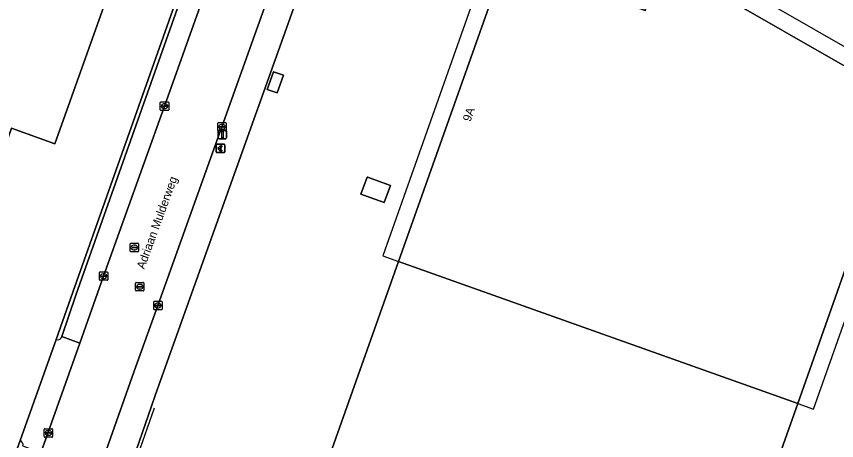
# Model space of a CAD drawing. Extents: x 155018 to 156648, y 383979 to 385733.
# Drawn here: x 155717.1 to 155814.3, y 385021.6 to 385071.8 of the extents above; entities that cross this region are included whole.
import ezdxf

# ---------------------------------------------------------------- set-up
doc = ezdxf.new("R2010")
doc.units = 0
for name, color, linetype in [('IMGEO_Betaalautomaat', 7, 'Continuous'), ('IMGEO_Erf', 7, 'Continuous'), ('IMGEO_Hek', 7, 'Continuous'), ('IMGEO_Kolk', 7, 'Continuous'), ('IMGEO_Lage_trafo', 7, 'Continuous'), ('IMGEO_Lichtmast', 7, 'Continuous'), ('IMGEO_Openbare_ruimte_label', 7, 'Continuous'), ('IMGEO_Pand', 7, 'Continuous'), ('IMGEO_Pand_nummerreeks', 7, 'Continuous'), ('IMGEO_Pand_overbouw', 7, 'Continuous'), ('IMGEO_Parkeervlak_open', 7, 'Continuous'), ('IMGEO_Rijbaan_lokaal_gesloten', 7, 'Continuous'), ('IMGEO_Rioolput', 7, 'Continuous'), ('IMGEO_Voetpad_open', 7, 'Continuous')]:
    doc.layers.add(name, color=color, linetype=linetype)

msp = doc.modelspace()

# ---------------------------------------------------------------- linework, layer by layer
at = {"layer": 'IMGEO_Betaalautomaat'}
for p, q in [((155740.767, 385055.78), (155740.767, 385056.621)), ((155740.767, 385056.621), (155740.767, 385055.78)), ((155740.842, 385056.704), (155741.683, 385056.704)), ((155741.683, 385056.704), (155740.842, 385056.704)), ((155741.05, 385056.168), (155741.05, 385056.236)), ((155741.171, 385056.236), (155741.171, 385056.168)), ((155741.429, 385056.509), (155741.412, 385056.409)), ((155741.416, 385056.003), (155741.438, 385055.916)), ((155741.766, 385056.63), (155741.766, 385055.789)), ((155741.766, 385055.789), (155741.766, 385056.63)), ((155741.692, 385055.705), (155740.851, 385055.705)), ((155740.851, 385055.705), (155741.692, 385055.705))]:
    msp.add_line(p, q, dxfattribs=at)
for points in [[(155741.05, 385056.236), (155740.981, 385056.236), (155740.981, 385056.305), (155741.06, 385056.305)], [(155741.055, 385056.099), (155740.981, 385056.099), (155740.981, 385056.168), (155741.05, 385056.168)], [(155741.182, 385056.305), (155741.329, 385056.305), (155741.329, 385056.236), (155741.171, 385056.236)], [(155741.171, 385056.168), (155741.329, 385056.168), (155741.329, 385056.099), (155741.185, 385056.099)]]:
    msp.add_lwpolyline(points, dxfattribs=at)
for centre, radius, start, end in [((155740.845, 385056.627), 0.0779, 92.4484, 184.28452), ((155740.845, 385056.627), 0.0779, 92.4484, 184.28452), ((155741.316, 385056.154), 0.267, 191.80956, 297.03891), ((155741.343, 385056.229), 0.293, 73.01398, 165.01395), ((155741.349, 385056.242), 0.179, 69.32359, 159.56827), ((155741.349, 385056.169), 0.179, 202.76249, 291.86925), ((155741.689, 385056.627), 0.0779, 2.4484, 94.28452), ((155741.689, 385056.627), 0.0779, 2.4484, 94.28452), ((155740.845, 385055.783), 0.0779, 182.4484, 274.28452), ((155740.845, 385055.783), 0.0779, 182.4484, 274.28452), ((155741.689, 385055.783), 0.0779, 272.4484, 4.28452), ((155741.689, 385055.783), 0.0779, 272.4484, 4.28452)]:
    msp.add_arc(centre, radius, start, end, dxfattribs=at)
at = {"layer": 'IMGEO_Erf'}
for points in [[(155694.342, 384956.978), (155694.915, 384958.585), (155709.077, 384998.076), (155709.767, 385000), (155717.522, 385021.627), (155721.797, 385033.581), (155723.78, 385039.191), (155749.439, 385111.623), (155754.279, 385125.284), (155751.396, 385130.416), (155717.596, 385142.395), (155670.014, 385159.249), (155661.245, 385162.355), (155620.236, 385176.93), (155602.298, 385183.305), (155601.269, 385183.671), (155551.448, 385201.401), (155546.604, 385198.733), (155542.42, 385187.249), (155529.708, 385151.464), (155526.702, 385143.011), (155526.061, 385141.208), (155524.297, 385136.458), (155523.434, 385136.779)], [(155841.725, 385076.189), (155812.458, 385090.276), (155811.925, 385090.532), (155810.841, 385091.052), (155764.43, 385113.324), (155764.255, 385112.835), (155733.568, 385027.069), (155733.054, 385025.589), (155730.642, 385018.653)], [(155753.183, 385017.001), (155762.359, 385042.817), (155775.007, 385078.407), (155791.593, 385072.523), (155793.619, 385078.32), (155822.361, 385061.864), (155809.649, 385026.028), (155797.027, 384990.446)]]:
    msp.add_lwpolyline(points, dxfattribs=at)
for points in [[(155670.263, 385124.691), (155674.13, 385128.38), (155672.13, 385129.15), (155674.66, 385131.64), (155676.67, 385130.92), (155681.04, 385135.1), (155695.29, 385130.022), (155721.45, 385120.7), (155719.12, 385114.03), (155729.74, 385110.24), (155731.69, 385106.03), (155727.91, 385095.51), (155734.56, 385093.08), (155727.662, 385073.693), (155721.63, 385056.74), (155716.5, 385058.59), (155715.32, 385055.2), (155712.89, 385057.75), (155713.52, 385059.62), (155709.03, 385061.25), (155718.594, 385088.148), (155701.503, 385094.257), (155707.612, 385111.348)], [(155747.968, 385062.78), (155746.814, 385063.191), (155747.549, 385065.252), (155748.711, 385064.866)], [(155757.908, 385050.806), (155758.646, 385052.82), (155758.671, 385052.811), (155761.411, 385051.807), (155760.673, 385049.793)]]:
    msp.add_lwpolyline(points, close=True, dxfattribs=at)
at = {"layer": 'IMGEO_Hek'}
msp.add_lwpolyline([(155733.417, 385025.46), (155730.074, 385015.981), (155724.402, 385000)], dxfattribs=at)
at = {"layer": 'IMGEO_Kolk'}
for p, q in [((155734.132, 385060.779), (155734.132, 385061.631)), ((155734.207, 385061.705), (155735.059, 385061.705)), ((155734.391, 385061.199), (155734.391, 385061.211)), ((155734.829, 385061.162), (155734.431, 385061.162)), ((155734.434, 385061.248), (155734.832, 385061.248)), ((155734.643, 385060.925), (155734.618, 385060.925)), ((155734.62, 385061.485), (155734.645, 385061.485)), ((155734.875, 385061.211), (155734.875, 385061.199)), ((155735.133, 385061.631), (155735.133, 385060.779)), ((155735.059, 385060.705), (155734.207, 385060.705)), ((155740.94, 385058.342), (155740.94, 385059.194)), ((155741.015, 385059.268), (155741.867, 385059.268)), ((155741.428, 385059.048), (155741.453, 385059.048)), ((155741.941, 385059.194), (155741.941, 385058.342)), ((155741.867, 385058.268), (155741.015, 385058.268)), ((155741.199, 385058.762), (155741.199, 385058.774)), ((155741.637, 385058.725), (155741.239, 385058.725)), ((155741.242, 385058.811), (155741.64, 385058.811)), ((155741.451, 385058.488), (155741.426, 385058.488)), ((155741.683, 385058.774), (155741.683, 385058.762)), ((155726.918, 385040.669), (155726.918, 385041.521)), ((155726.993, 385041.595), (155727.845, 385041.595)), ((155727.406, 385041.375), (155727.431, 385041.375)), ((155727.919, 385041.521), (155727.919, 385040.669)), ((155727.845, 385040.595), (155726.993, 385040.595)), ((155727.177, 385041.089), (155727.177, 385041.101)), ((155727.615, 385041.052), (155727.217, 385041.052)), ((155727.22, 385041.138), (155727.618, 385041.138)), ((155727.429, 385040.815), (155727.404, 385040.815)), ((155727.661, 385041.101), (155727.661, 385041.089)), ((155733.348, 385037.188), (155733.348, 385038.04)), ((155733.423, 385038.114), (155734.275, 385038.114)), ((155733.607, 385037.608), (155733.607, 385037.62)), ((155734.045, 385037.571), (155733.647, 385037.571)), ((155733.65, 385037.657), (155734.048, 385037.657)), ((155733.836, 385037.894), (155733.861, 385037.894)), ((155734.091, 385037.62), (155734.091, 385037.608)), ((155734.349, 385038.04), (155734.349, 385037.188)), ((155734.275, 385037.114), (155733.423, 385037.114)), ((155733.859, 385037.334), (155733.834, 385037.334)), ((155720.374, 385022.102), (155720.374, 385022.954)), ((155720.449, 385023.028), (155721.301, 385023.028)), ((155721.375, 385022.954), (155721.375, 385022.102)), ((155721.301, 385022.028), (155720.449, 385022.028)), ((155720.633, 385022.522), (155720.633, 385022.534)), ((155721.071, 385022.485), (155720.673, 385022.485)), ((155720.676, 385022.571), (155721.074, 385022.571)), ((155720.885, 385022.248), (155720.86, 385022.248)), ((155720.862, 385022.808), (155720.887, 385022.808)), ((155721.117, 385022.534), (155721.117, 385022.522))]:
    msp.add_line(p, q, dxfattribs=at)
for points in [[(155734.132, 385060.779), (155734.132, 385061.631)], [(155734.207, 385061.705), (155735.059, 385061.705)], [(155735.133, 385061.631), (155735.133, 385060.779)], [(155735.059, 385060.705), (155734.207, 385060.705)], [(155740.94, 385058.342), (155740.94, 385059.194)], [(155741.015, 385059.268), (155741.867, 385059.268)], [(155741.941, 385059.194), (155741.941, 385058.342)], [(155741.867, 385058.268), (155741.015, 385058.268)], [(155726.918, 385040.669), (155726.918, 385041.521)], [(155726.993, 385041.595), (155727.845, 385041.595)], [(155727.919, 385041.521), (155727.919, 385040.669)], [(155727.845, 385040.595), (155726.993, 385040.595)], [(155733.348, 385037.188), (155733.348, 385038.04)], [(155733.423, 385038.114), (155734.275, 385038.114)], [(155734.349, 385038.04), (155734.349, 385037.188)], [(155734.275, 385037.114), (155733.423, 385037.114)], [(155720.374, 385022.102), (155720.374, 385022.954)], [(155720.449, 385023.028), (155721.301, 385023.028)], [(155721.375, 385022.954), (155721.375, 385022.102)], [(155721.301, 385022.028), (155720.449, 385022.028)]]:
    msp.add_lwpolyline(points, dxfattribs=at)
for centre, radius, start, end in [((155734.209, 385061.629), 0.0765, 91.55205, 178.44795), ((155734.209, 385061.629), 0.0765, 91.55205, 178.44795), ((155734.431, 385061.208), 0.0403, 85.87752, 175.75265), ((155734.428, 385061.198), 0.0366, 178.93798, 274.71019), ((155734.832, 385061.205), 0.043, 264.86636, 352.45326), ((155734.836, 385061.21), 0.0386, 1.73085, 96.63898), ((155735.057, 385061.629), 0.0765, 1.55205, 88.44795), ((155735.057, 385061.629), 0.0765, 1.55205, 88.44795), ((155734.209, 385060.781), 0.0765, 181.55205, 268.44795), ((155734.209, 385060.781), 0.0765, 181.55205, 268.44795), ((155735.057, 385060.781), 0.0765, 271.55205, 358.44795), ((155735.057, 385060.781), 0.0765, 271.55205, 358.44795), ((155741.017, 385059.192), 0.0765, 91.55205, 178.44795), ((155741.017, 385059.192), 0.0765, 91.55205, 178.44795), ((155741.865, 385059.192), 0.0765, 1.55205, 88.44795), ((155741.865, 385059.192), 0.0765, 1.55205, 88.44795), ((155741.017, 385058.344), 0.0765, 181.55205, 268.44795), ((155741.017, 385058.344), 0.0765, 181.55205, 268.44795), ((155741.239, 385058.771), 0.0403, 85.87752, 175.75265), ((155741.236, 385058.761), 0.0366, 178.93798, 274.71019), ((155741.64, 385058.768), 0.043, 264.86636, 352.45326), ((155741.644, 385058.773), 0.0386, 1.73085, 96.63898), ((155741.865, 385058.344), 0.0765, 271.55205, 358.44795), ((155741.865, 385058.344), 0.0765, 271.55205, 358.44795), ((155726.995, 385041.519), 0.0765, 91.55205, 178.44795), ((155726.995, 385041.519), 0.0765, 91.55205, 178.44795), ((155727.843, 385041.519), 0.0765, 1.55205, 88.44795), ((155727.843, 385041.519), 0.0765, 1.55205, 88.44795), ((155726.995, 385040.671), 0.0765, 181.55205, 268.44795), ((155726.995, 385040.671), 0.0765, 181.55205, 268.44795), ((155727.217, 385041.098), 0.0403, 85.87752, 175.75265), ((155727.214, 385041.088), 0.0366, 178.93798, 274.71019), ((155727.618, 385041.095), 0.043, 264.86636, 352.45326), ((155727.622, 385041.1), 0.0386, 1.73085, 96.63898), ((155727.843, 385040.671), 0.0765, 271.55205, 358.44795), ((155727.843, 385040.671), 0.0765, 271.55205, 358.44795), ((155733.425, 385038.038), 0.0765, 91.55205, 178.44795), ((155733.425, 385038.038), 0.0765, 91.55205, 178.44795), ((155733.647, 385037.617), 0.0403, 85.87752, 175.75265), ((155733.644, 385037.607), 0.0366, 178.93798, 274.71019), ((155734.048, 385037.614), 0.043, 264.86636, 352.45326), ((155734.052, 385037.619), 0.0386, 1.73085, 96.63898), ((155734.273, 385038.038), 0.0765, 1.55205, 88.44795), ((155734.273, 385038.038), 0.0765, 1.55205, 88.44795), ((155733.425, 385037.19), 0.0765, 181.55205, 268.44795), ((155733.425, 385037.19), 0.0765, 181.55205, 268.44795), ((155734.273, 385037.19), 0.0765, 271.55205, 358.44795), ((155734.273, 385037.19), 0.0765, 271.55205, 358.44795), ((155720.451, 385022.952), 0.0765, 91.55205, 178.44795), ((155720.451, 385022.952), 0.0765, 91.55205, 178.44795), ((155721.299, 385022.952), 0.0765, 1.55205, 88.44795), ((155721.299, 385022.952), 0.0765, 1.55205, 88.44795), ((155720.451, 385022.104), 0.0765, 181.55205, 268.44795), ((155720.451, 385022.104), 0.0765, 181.55205, 268.44795), ((155720.673, 385022.531), 0.0403, 85.87752, 175.75265), ((155720.67, 385022.521), 0.0366, 178.93798, 274.71019), ((155721.074, 385022.528), 0.043, 264.86636, 352.45326), ((155721.078, 385022.533), 0.0386, 1.73085, 96.63898), ((155721.299, 385022.104), 0.0765, 271.55205, 358.44795), ((155721.299, 385022.104), 0.0765, 271.55205, 358.44795)]:
    msp.add_arc(centre, radius, start, end, dxfattribs=at)
for centre, major_axis, ratio, start_param, end_param in [((155734.619, 385061.205), (-0.387, 0.002), 0.722429, 4.712389, 7.853982), ((155734.644, 385061.205), (-0.39, 0.002), 0.717154, 1.570796, 4.712389), ((155741.427, 385058.768), (-0.387, 0.002), 0.722429, 4.712389, 7.853982), ((155741.452, 385058.768), (-0.39, 0.002), 0.717154, 1.570796, 4.712389), ((155727.405, 385041.095), (-0.387, 0.002), 0.722429, 4.712389, 7.853982), ((155727.43, 385041.095), (-0.39, 0.002), 0.717154, 1.570796, 4.712389), ((155733.835, 385037.614), (-0.387, 0.002), 0.722429, 4.712389, 7.853982), ((155733.86, 385037.614), (-0.39, 0.002), 0.717154, 1.570796, 4.712389), ((155720.861, 385022.528), (-0.387, 0.002), 0.722429, 4.712389, 7.853982), ((155720.886, 385022.528), (-0.39, 0.002), 0.717154, 1.570796, 4.712389)]:
    msp.add_ellipse(centre, major_axis=major_axis, ratio=ratio, start_param=start_param, end_param=end_param, dxfattribs=at)
at = {"layer": 'IMGEO_Lage_trafo'}
for points in [[(155747.549, 385065.252), (155746.814, 385063.191), (155747.968, 385062.78), (155748.711, 385064.866)], [(155758.646, 385052.82), (155757.908, 385050.806), (155760.673, 385049.793), (155761.411, 385051.807), (155758.671, 385052.811)]]:
    msp.add_lwpolyline(points, close=True, dxfattribs=at)
at = {"layer": 'IMGEO_Lichtmast'}
for p, q in [((155740.995, 385057.449), (155740.995, 385058.249)), ((155740.995, 385058.249), (155740.995, 385057.449)), ((155741.095, 385058.349), (155741.885, 385058.349)), ((155741.885, 385058.349), (155741.095, 385058.349)), ((155741.985, 385058.249), (155741.985, 385057.449)), ((155741.985, 385057.449), (155741.985, 385058.249)), ((155741.885, 385057.349), (155741.095, 385057.349)), ((155741.095, 385057.349), (155741.885, 385057.349))]:
    msp.add_line(p, q, dxfattribs=at)
msp.add_lwpolyline([(155741.415, 385058.224), (155741.565, 385058.224), (155741.565, 385057.474), (155741.415, 385057.474), (155741.415, 385058.224)], dxfattribs=at)
for centre, start, end in [((155741.095, 385058.249), 90, 180), ((155741.095, 385058.249), 90, 180), ((155741.885, 385058.249), 0, 90), ((155741.885, 385058.249), 360, 90), ((155741.095, 385057.449), 180, 270), ((155741.095, 385057.449), 180, 270), ((155741.885, 385057.449), 270, 0), ((155741.885, 385057.449), 270, 0)]:
    msp.add_arc(centre, 0.1, start, end, dxfattribs=at)
at = {"layer": 'IMGEO_Pand'}
for points in [[(155695.29, 385130.022), (155681.04, 385135.1), (155676.67, 385130.92), (155674.66, 385131.64), (155672.13, 385129.15), (155674.13, 385128.38), (155670.263, 385124.691), (155707.612, 385111.348), (155701.503, 385094.257), (155718.594, 385088.148), (155709.03, 385061.25), (155713.52, 385059.62), (155712.89, 385057.75), (155715.32, 385055.2), (155716.5, 385058.59), (155721.63, 385056.74), (155727.662, 385073.693), (155734.56, 385093.08), (155727.91, 385095.51), (155731.69, 385106.03), (155729.74, 385110.24), (155719.12, 385114.03), (155721.45, 385120.7)], [(155822.361, 385061.864), (155793.619, 385078.32), (155791.593, 385072.523), (155775.007, 385078.407), (155762.359, 385042.817), (155809.649, 385026.028)]]:
    msp.add_lwpolyline(points, close=True, dxfattribs=at)
msp.add_lwpolyline([(155828.255, 384911.336), (155796.179, 384922.734), (155808.139, 384956.274), (155787.494, 384963.57), (155797.027, 384990.446), (155809.649, 385026.028), (155762.359, 385042.817), (155753.183, 385017.001), (155750.623, 385009.797), (155749.138, 385010.33), (155747.33, 385005.279), (155748.837, 385004.772), (155746.303, 384997.642), (155740.174, 384980.395), (155728.915, 384948.717), (155727.468, 384949.235), (155696.765, 384862.93), (155766.348, 384838.189), (155767.038, 384840.129), (155767.438, 384839.985), (155765.854, 384835.53), (155771.729, 384833.45), (155773.299, 384837.894), (155819.22, 384821.585)], dxfattribs=at)
at = {"layer": 'IMGEO_Pand_overbouw'}
msp.add_lwpolyline([(155824.79, 385062.761), (155777.024, 385090.129), (155760.494, 385043.478), (155762.359, 385042.817), (155775.007, 385078.407), (155791.593, 385072.523), (155793.619, 385078.32), (155822.361, 385061.864), (155809.649, 385026.028), (155811.531, 385025.362)], close=True, dxfattribs=at)
at = {"layer": 'IMGEO_Parkeervlak_open'}
for points in [[(155749.712, 385111.016), (155724.175, 385038.957), (155722.456, 385033.926), (155724.606, 385033.163), (155727.42, 385041.095), (155734.635, 385061.204)], [(155734.635, 385061.204), (155741.863, 385081.49), (155749.126, 385101.756), (155752.407, 385110.986)]]:
    msp.add_lwpolyline(points, dxfattribs=at)
at = {"layer": 'IMGEO_Rijbaan_lokaal_gesloten'}
for points in [[(155764.837, 385117.429), (155755.507, 385119.738), (155752.407, 385110.986), (155749.126, 385101.756), (155741.863, 385081.49), (155734.635, 385061.204), (155727.42, 385041.095), (155724.606, 385033.163), (155719.998, 385020.177), (155712.839, 385000), (155711.66, 384996.694), (155697.277, 384956.434), (155683.176, 384916.819), (155680.471, 384909.27), (155672.406, 384886.601)], [(155679.062, 384884.306), (155679.409, 384885.386), (155683.078, 384895.663), (155693.322, 384923.959), (155698.719, 384939.029), (155712.551, 384977.822), (155712.738, 384978.347), (155715.089, 384984.941), (155720.459, 385000), (155723.632, 385008.98), (155724.976, 385012.761), (155727.017, 385018.428), (155728.003, 385021.255), (155731.055, 385029.838), (155733.848, 385037.615), (155741.439, 385058.768), (155756.537, 385101.063), (155759.644, 385109.754)]]:
    msp.add_lwpolyline(points, dxfattribs=at)
at = {"layer": 'IMGEO_Rioolput'}
for p, q in [((155730.561, 385044.051), (155730.561, 385044.903)), ((155730.636, 385044.977), (155731.488, 385044.977)), ((155730.82, 385044.471), (155730.82, 385044.483)), ((155731.258, 385044.434), (155730.86, 385044.434)), ((155730.863, 385044.52), (155731.261, 385044.52)), ((155731.049, 385044.757), (155731.074, 385044.757)), ((155731.304, 385044.483), (155731.304, 385044.471)), ((155731.562, 385044.903), (155731.562, 385044.051)), ((155731.488, 385043.977), (155730.636, 385043.977)), ((155731.072, 385044.197), (155731.047, 385044.197)), ((155731.199, 385039.414), (155731.199, 385040.266)), ((155731.274, 385040.34), (155732.126, 385040.34)), ((155731.458, 385039.834), (155731.458, 385039.846)), ((155731.896, 385039.797), (155731.498, 385039.797)), ((155731.501, 385039.883), (155731.899, 385039.883)), ((155731.71, 385039.56), (155731.685, 385039.56)), ((155731.687, 385040.12), (155731.712, 385040.12)), ((155731.942, 385039.846), (155731.942, 385039.834)), ((155732.2, 385040.266), (155732.2, 385039.414)), ((155732.126, 385039.34), (155731.274, 385039.34))]:
    msp.add_line(p, q, dxfattribs=at)
for points in [[(155730.561, 385044.051), (155730.561, 385044.903)], [(155730.636, 385044.977), (155731.488, 385044.977)], [(155731.562, 385044.903), (155731.562, 385044.051)], [(155731.488, 385043.977), (155730.636, 385043.977)], [(155731.199, 385039.414), (155731.199, 385040.266)], [(155731.274, 385040.34), (155732.126, 385040.34)], [(155732.2, 385040.266), (155732.2, 385039.414)], [(155732.126, 385039.34), (155731.274, 385039.34)]]:
    msp.add_lwpolyline(points, dxfattribs=at)
for centre, radius, start, end in [((155730.638, 385044.901), 0.0765, 91.55205, 178.44795), ((155730.638, 385044.901), 0.0765, 91.55205, 178.44795), ((155730.86, 385044.48), 0.0403, 85.87752, 175.75265), ((155730.857, 385044.47), 0.0366, 178.93798, 274.71019), ((155731.261, 385044.477), 0.043, 264.86636, 352.45326), ((155731.265, 385044.482), 0.0386, 1.73085, 96.63898), ((155731.486, 385044.901), 0.0765, 1.55205, 88.44795), ((155731.486, 385044.901), 0.0765, 1.55205, 88.44795), ((155730.638, 385044.053), 0.0765, 181.55205, 268.44795), ((155730.638, 385044.053), 0.0765, 181.55205, 268.44795), ((155731.486, 385044.053), 0.0765, 271.55205, 358.44795), ((155731.486, 385044.053), 0.0765, 271.55205, 358.44795), ((155731.276, 385040.264), 0.0765, 91.55205, 178.44795), ((155731.276, 385040.264), 0.0765, 91.55205, 178.44795), ((155731.498, 385039.843), 0.0403, 85.87752, 175.75265), ((155731.495, 385039.833), 0.0366, 178.93798, 274.71019), ((155731.899, 385039.84), 0.043, 264.86636, 352.45326), ((155731.903, 385039.845), 0.0386, 1.73085, 96.63898), ((155732.124, 385040.264), 0.0765, 1.55205, 88.44795), ((155732.124, 385040.264), 0.0765, 1.55205, 88.44795), ((155731.276, 385039.416), 0.0765, 181.55205, 268.44795), ((155731.276, 385039.416), 0.0765, 181.55205, 268.44795), ((155732.124, 385039.416), 0.0765, 271.55205, 358.44795), ((155732.124, 385039.416), 0.0765, 271.55205, 358.44795)]:
    msp.add_arc(centre, radius, start, end, dxfattribs=at)
for centre, major_axis, ratio, start_param, end_param in [((155731.048, 385044.477), (-0.387, 0.002), 0.722429, 4.712389, 7.853982), ((155731.073, 385044.477), (-0.39, 0.002), 0.717154, 1.570796, 4.712389), ((155731.686, 385039.84), (-0.387, 0.002), 0.722429, 4.712389, 7.853982), ((155731.711, 385039.84), (-0.39, 0.002), 0.717154, 1.570796, 4.712389)]:
    msp.add_ellipse(centre, major_axis=major_axis, ratio=ratio, start_param=start_param, end_param=end_param, dxfattribs=at)
at = {"layer": 'IMGEO_Voetpad_open'}
for points in [[(155759.644, 385109.754), (155756.537, 385101.063), (155741.439, 385058.768), (155733.848, 385037.615), (155731.055, 385029.838), (155728.003, 385021.255), (155727.017, 385018.428), (155728.134, 385018.023), (155726.108, 385012.352), (155724.976, 385012.761), (155723.632, 385008.98), (155720.459, 385000), (155715.089, 384984.941), (155718.276, 384983.804), (155724.057, 385000), (155730.413, 385017.993), (155730.642, 385018.653), (155733.054, 385025.589), (155733.568, 385027.069), (155764.255, 385112.835)], [(155750.359, 385111.297), (155750.315, 385111.323), (155749.439, 385111.623), (155723.78, 385039.191), (155721.797, 385033.581)], [(155722.426, 385033.838), (155722.456, 385033.926), (155724.175, 385038.957), (155749.712, 385111.016)], [(155724.606, 385033.163), (155722.456, 385033.926), (155722.426, 385033.838)], [(155721.797, 385033.581), (155717.522, 385021.627)], [(155717.863, 385020.989), (155719.998, 385020.177), (155724.606, 385033.163)], [(155717.522, 385021.627), (155709.767, 385000), (155709.077, 384998.076), (155710.043, 384997.728), (155710.061, 384997.723)]]:
    msp.add_lwpolyline(points, dxfattribs=at)
for centre, radius, start, end in [((155721.967, 385034.064), 0.512, 250.6501, 333.79828), ((155721.967, 385034.064), 0.512, 250.6501, 333.79828), ((155717.35, 385021.125), 0.531, 345.18274, 71.06473), ((155717.35, 385021.125), 0.531, 345.18274, 71.06473)]:
    msp.add_arc(centre, radius, start, end, dxfattribs=at)

# ---------------------------------------------------------------- texts
at = {"layer": 'IMGEO_Openbare_ruimte_label'}
msp.add_text('Adriaan Mulderweg', height=1, rotation=70.00711, dxfattribs=at).set_placement((155732.234, 385041.843))
at = {"layer": 'IMGEO_Pand_nummerreeks'}
msp.add_text('9A', height=1, rotation=70.4337, dxfattribs=at).set_placement((155770.87, 385059.299))

doc.saveas('drawing.dxf')
